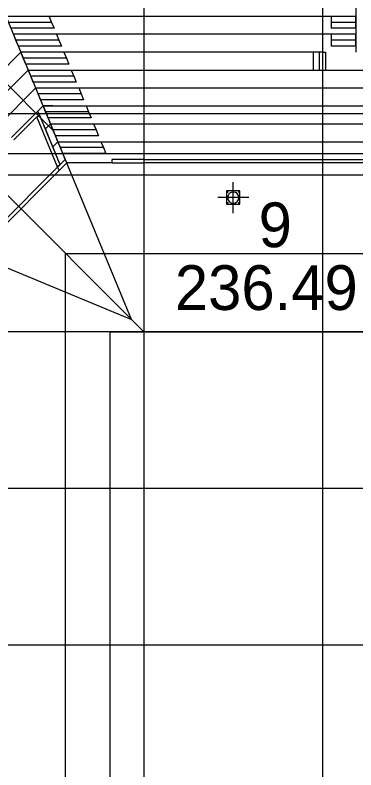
# Model space of a CAD drawing. Extents: x -264165 to -263575, y -1242333 to -1242036.
# Drawn here: x -263890.22 to -263874.98, y -1242131.46 to -1242097.73 of the extents above; entities that cross this region are included whole.
import ezdxf

# ---------------------------------------------------------------- set-up
doc = ezdxf.new("R2010")
doc.units = 0
for name, color, linetype in [('KFA_BODY_VYTYCOVAK', 7, 'Continuous'), ('KFA_HESCON_OSI_STAVBY', 7, 'Continuous'), ('KFA_SITUACIA_DRS_VYTYCOVAK_SEDA', 7, 'Continuous')]:
    doc.layers.add(name, color=color, linetype=linetype)

msp = doc.modelspace()

# ---------------------------------------------------------------- linework, layer by layer
at = {"layer": 'KFA_HESCON_OSI_STAVBY'}
for p, q in [((-263884.468, -1242080.447), (-263884.468, -1242248.737)), ((-263876.468, -1242080.447), (-263876.468, -1242248.737)), ((-263906.568, -1242084.832), (-263888.515, -1242102.885)), ((-263884.468, -1242111.882), (-263909.043, -1242087.307)), ((-263885.015, -1242111.335), (-263894.968, -1242087.307)), ((-263909.043, -1242101.382), (-263885.015, -1242111.335)), ((-263787.486, -1242102.132), (-263921.823, -1242102.132)), ((-263787.486, -1242103.932), (-263921.823, -1242103.932)), ((-263787.486, -1242104.882), (-263921.823, -1242104.882)), ((-263787.486, -1242111.882), (-263921.823, -1242111.882)), ((-263884.468, -1242111.882), (-263884.468, -1242111.882)), ((-263787.486, -1242118.882), (-263921.823, -1242118.882)), ((-263787.486, -1242125.882), (-263921.823, -1242125.882))]:
    msp.add_line(p, q, dxfattribs=at)
at = {"layer": 'KFA_SITUACIA_DRS_VYTYCOVAK_SEDA'}
for p, q in [((-263874.98, -1242096.982), (-263874.98, -1242097.782)), ((-263874.98, -1242096.982), (-263874.98, -1242097.782)), ((-263884.468, -1242097.782), (-263890.629, -1242097.782)), ((-263884.468, -1242097.782), (-263890.629, -1242097.782)), ((-263888.593, -1242098.049), (-263890.518, -1242098.049)), ((-263888.593, -1242098.049), (-263890.518, -1242098.049)), ((-263888.704, -1242097.782), (-263888.593, -1242098.049)), ((-263888.704, -1242097.782), (-263888.593, -1242098.049)), ((-263888.593, -1242098.049), (-263888.483, -1242098.316)), ((-263888.593, -1242098.049), (-263888.483, -1242098.316)), ((-263876.468, -1242097.782), (-263884.468, -1242097.782)), ((-263876.468, -1242097.782), (-263884.468, -1242097.782)), ((-263874.98, -1242097.782), (-263876.468, -1242097.782)), ((-263874.98, -1242097.782), (-263876.468, -1242097.782)), ((-263876.081, -1242097.782), (-263876.081, -1242098.049)), ((-263876.081, -1242097.782), (-263876.081, -1242098.049)), ((-263874.981, -1242098.049), (-263876.081, -1242098.049)), ((-263874.981, -1242098.049), (-263876.081, -1242098.049)), ((-263876.081, -1242098.049), (-263876.081, -1242098.316)), ((-263876.081, -1242098.049), (-263876.081, -1242098.316)), ((-263874.981, -1242098.049), (-263874.981, -1242097.782)), ((-263874.981, -1242098.049), (-263874.981, -1242097.782)), ((-263874.981, -1242098.316), (-263874.981, -1242098.049)), ((-263874.981, -1242098.316), (-263874.981, -1242098.049)), ((-263874.98, -1242097.782), (-263874.98, -1242098.582)), ((-263874.98, -1242097.782), (-263874.98, -1242098.582)), ((-263888.483, -1242098.316), (-263890.408, -1242098.316)), ((-263888.483, -1242098.316), (-263890.408, -1242098.316)), ((-263874.981, -1242098.316), (-263876.081, -1242098.316)), ((-263874.981, -1242098.316), (-263876.081, -1242098.316)), ((-263890.187, -1242098.849), (-263890.298, -1242098.582)), ((-263890.187, -1242098.849), (-263890.298, -1242098.582)), ((-263884.468, -1242098.582), (-263890.298, -1242098.582)), ((-263884.468, -1242098.582), (-263890.298, -1242098.582)), ((-263888.373, -1242098.582), (-263888.262, -1242098.849)), ((-263888.373, -1242098.582), (-263888.262, -1242098.849)), ((-263876.468, -1242098.582), (-263884.468, -1242098.582)), ((-263876.468, -1242098.582), (-263884.468, -1242098.582)), ((-263874.98, -1242098.582), (-263876.468, -1242098.582)), ((-263874.98, -1242098.582), (-263876.468, -1242098.582)), ((-263876.081, -1242098.582), (-263876.081, -1242098.849)), ((-263876.081, -1242098.582), (-263876.081, -1242098.849)), ((-263874.981, -1242098.849), (-263874.981, -1242098.582)), ((-263874.981, -1242098.849), (-263874.981, -1242098.582)), ((-263874.98, -1242098.582), (-263874.98, -1242099.382)), ((-263874.98, -1242098.582), (-263874.98, -1242099.382)), ((-263890.077, -1242099.116), (-263890.187, -1242098.849)), ((-263890.077, -1242099.116), (-263890.187, -1242098.849)), ((-263888.262, -1242098.849), (-263890.187, -1242098.849)), ((-263888.262, -1242098.849), (-263890.187, -1242098.849)), ((-263888.262, -1242098.849), (-263888.152, -1242099.116)), ((-263888.262, -1242098.849), (-263888.152, -1242099.116)), ((-263874.981, -1242098.849), (-263876.081, -1242098.849)), ((-263874.981, -1242098.849), (-263876.081, -1242098.849)), ((-263876.081, -1242098.849), (-263876.081, -1242099.116)), ((-263876.081, -1242098.849), (-263876.081, -1242099.116)), ((-263874.981, -1242099.116), (-263874.981, -1242098.849)), ((-263874.981, -1242099.116), (-263874.981, -1242098.849)), ((-263889.966, -1242099.382), (-263891.204, -1242100.62)), ((-263889.966, -1242099.382), (-263891.204, -1242100.62)), ((-263888.152, -1242099.116), (-263890.077, -1242099.116)), ((-263888.152, -1242099.116), (-263890.077, -1242099.116)), ((-263889.856, -1242099.649), (-263889.966, -1242099.382)), ((-263889.856, -1242099.649), (-263889.966, -1242099.382)), ((-263889.056, -1242099.382), (-263889.966, -1242099.382)), ((-263889.056, -1242099.382), (-263889.966, -1242099.382)), ((-263884.468, -1242099.382), (-263889.966, -1242099.382)), ((-263884.468, -1242099.382), (-263889.966, -1242099.382)), ((-263888.041, -1242099.382), (-263887.931, -1242099.649)), ((-263888.041, -1242099.382), (-263887.931, -1242099.649)), ((-263876.468, -1242099.382), (-263884.468, -1242099.382)), ((-263876.468, -1242099.382), (-263884.468, -1242099.382)), ((-263876.881, -1242100.182), (-263876.881, -1242099.382)), ((-263876.881, -1242100.182), (-263876.881, -1242099.382)), ((-263876.614, -1242100.182), (-263876.614, -1242099.382)), ((-263876.614, -1242100.182), (-263876.614, -1242099.382)), ((-263876.468, -1242099.382), (-263876.347, -1242099.382)), ((-263876.468, -1242099.382), (-263876.347, -1242099.382)), ((-263876.347, -1242099.382), (-263876.347, -1242100.182)), ((-263876.347, -1242099.382), (-263876.347, -1242100.182)), ((-263874.981, -1242099.116), (-263876.081, -1242099.116)), ((-263874.981, -1242099.116), (-263876.081, -1242099.116)), ((-263889.745, -1242099.916), (-263889.856, -1242099.649)), ((-263889.745, -1242099.916), (-263889.856, -1242099.649)), ((-263887.931, -1242099.649), (-263889.856, -1242099.649)), ((-263887.931, -1242099.649), (-263889.856, -1242099.649)), ((-263887.931, -1242099.649), (-263887.82, -1242099.916)), ((-263887.931, -1242099.649), (-263887.82, -1242099.916)), ((-263887.82, -1242099.916), (-263889.745, -1242099.916)), ((-263887.82, -1242099.916), (-263889.745, -1242099.916)), ((-263890.639, -1242101.186), (-263889.635, -1242100.182)), ((-263890.639, -1242101.186), (-263889.635, -1242100.182)), ((-263889.524, -1242100.449), (-263889.635, -1242100.182)), ((-263889.524, -1242100.449), (-263889.635, -1242100.182)), ((-263889.635, -1242100.182), (-263884.468, -1242100.182)), ((-263889.635, -1242100.182), (-263884.468, -1242100.182)), ((-263887.71, -1242100.182), (-263887.599, -1242100.449)), ((-263887.71, -1242100.182), (-263887.599, -1242100.449)), ((-263884.468, -1242100.182), (-263876.468, -1242100.182)), ((-263884.468, -1242100.182), (-263876.468, -1242100.182)), ((-263876.881, -1242100.182), (-263876.614, -1242100.182)), ((-263876.881, -1242100.182), (-263876.614, -1242100.182)), ((-263876.614, -1242100.182), (-263876.347, -1242100.182)), ((-263876.614, -1242100.182), (-263876.347, -1242100.182)), ((-263876.468, -1242100.182), (-263869.468, -1242100.182)), ((-263876.468, -1242100.182), (-263869.468, -1242100.182)), ((-263876.347, -1242100.182), (-263873.518, -1242100.182)), ((-263876.347, -1242100.182), (-263873.518, -1242100.182)), ((-263889.414, -1242100.716), (-263889.524, -1242100.449)), ((-263889.414, -1242100.716), (-263889.524, -1242100.449)), ((-263887.599, -1242100.449), (-263889.524, -1242100.449)), ((-263887.599, -1242100.449), (-263889.524, -1242100.449)), ((-263887.489, -1242100.716), (-263889.414, -1242100.716)), ((-263887.489, -1242100.716), (-263889.414, -1242100.716)), ((-263887.599, -1242100.449), (-263887.489, -1242100.716)), ((-263887.599, -1242100.449), (-263887.489, -1242100.716)), ((-263890.957, -1242102.636), (-263889.303, -1242100.982)), ((-263890.957, -1242102.636), (-263889.303, -1242100.982)), ((-263889.193, -1242101.249), (-263889.303, -1242100.982)), ((-263889.193, -1242101.249), (-263889.303, -1242100.982)), ((-263889.303, -1242100.982), (-263884.468, -1242100.982)), ((-263889.303, -1242100.982), (-263884.468, -1242100.982)), ((-263887.378, -1242100.982), (-263887.268, -1242101.249)), ((-263887.378, -1242100.982), (-263887.268, -1242101.249)), ((-263884.468, -1242100.982), (-263876.468, -1242100.982)), ((-263884.468, -1242100.982), (-263876.468, -1242100.982)), ((-263876.468, -1242100.982), (-263869.468, -1242100.982)), ((-263876.468, -1242100.982), (-263869.468, -1242100.982)), ((-263889.083, -1242101.516), (-263889.193, -1242101.249)), ((-263889.083, -1242101.516), (-263889.193, -1242101.249)), ((-263887.268, -1242101.249), (-263889.193, -1242101.249)), ((-263887.268, -1242101.249), (-263889.193, -1242101.249)), ((-263887.268, -1242101.249), (-263887.158, -1242101.516)), ((-263887.268, -1242101.249), (-263887.158, -1242101.516)), ((-263887.158, -1242101.516), (-263889.083, -1242101.516)), ((-263887.158, -1242101.516), (-263889.083, -1242101.516)), ((-263889.202, -1242102.012), (-263889.316, -1242102.127)), ((-263889.202, -1242102.012), (-263889.316, -1242102.127)), ((-263889.202, -1242102.012), (-263888.972, -1242101.782)), ((-263889.202, -1242102.012), (-263888.972, -1242101.782)), ((-263889.202, -1242102.012), (-263888.972, -1242101.782)), ((-263889.202, -1242102.012), (-263888.972, -1242101.782)), ((-263888.87, -1242102.812), (-263889.202, -1242102.012)), ((-263888.87, -1242102.812), (-263889.202, -1242102.012)), ((-263889.116, -1242102.219), (-263889.202, -1242102.012)), ((-263889.116, -1242102.219), (-263889.202, -1242102.012)), ((-263888.862, -1242102.049), (-263888.972, -1242101.782)), ((-263888.862, -1242102.049), (-263888.972, -1242101.782)), ((-263888.543, -1242101.782), (-263888.972, -1242101.782)), ((-263888.543, -1242101.782), (-263888.972, -1242101.782)), ((-263888.972, -1242101.782), (-263888.641, -1242102.582)), ((-263888.972, -1242101.782), (-263888.641, -1242102.582)), ((-263888.972, -1242101.782), (-263884.468, -1242101.782)), ((-263888.972, -1242101.782), (-263884.468, -1242101.782)), ((-263888.751, -1242102.316), (-263888.862, -1242102.049)), ((-263888.751, -1242102.316), (-263888.862, -1242102.049)), ((-263886.937, -1242102.049), (-263888.862, -1242102.049)), ((-263886.937, -1242102.049), (-263888.862, -1242102.049)), ((-263887.047, -1242101.782), (-263886.937, -1242102.049)), ((-263887.047, -1242101.782), (-263886.937, -1242102.049)), ((-263886.937, -1242102.049), (-263886.826, -1242102.316)), ((-263886.937, -1242102.049), (-263886.826, -1242102.316)), ((-263884.468, -1242101.782), (-263876.468, -1242101.782)), ((-263884.468, -1242101.782), (-263876.468, -1242101.782)), ((-263876.468, -1242101.782), (-263869.468, -1242101.782)), ((-263876.468, -1242101.782), (-263869.468, -1242101.782)), ((-263890.391, -1242103.201), (-263889.316, -1242102.127)), ((-263890.391, -1242103.201), (-263889.316, -1242102.127)), ((-263889.254, -1242102.277), (-263890.285, -1242103.307)), ((-263889.254, -1242102.277), (-263890.285, -1242103.307)), ((-263889.254, -1242102.277), (-263889.116, -1242102.219)), ((-263889.254, -1242102.277), (-263889.116, -1242102.219)), ((-263888.346, -1242104.469), (-263889.254, -1242102.277)), ((-263888.346, -1242104.469), (-263889.254, -1242102.277)), ((-263888.208, -1242104.412), (-263889.116, -1242102.219)), ((-263888.208, -1242104.412), (-263889.116, -1242102.219)), ((-263886.826, -1242102.316), (-263888.751, -1242102.316)), ((-263886.826, -1242102.316), (-263888.751, -1242102.316)), ((-263888.641, -1242102.582), (-263888.751, -1242102.316)), ((-263888.641, -1242102.582), (-263888.751, -1242102.316)), ((-263888.87, -1242102.812), (-263888.641, -1242102.582)), ((-263888.87, -1242102.812), (-263888.641, -1242102.582)), ((-263888.53, -1242102.849), (-263888.641, -1242102.582)), ((-263888.53, -1242102.849), (-263888.641, -1242102.582)), ((-263888.641, -1242102.582), (-263888.309, -1242103.382)), ((-263888.641, -1242102.582), (-263888.309, -1242103.382)), ((-263888.641, -1242102.582), (-263884.468, -1242102.582)), ((-263888.641, -1242102.582), (-263884.468, -1242102.582)), ((-263886.716, -1242102.582), (-263886.605, -1242102.849)), ((-263886.716, -1242102.582), (-263886.605, -1242102.849)), ((-263884.468, -1242102.582), (-263876.468, -1242102.582)), ((-263884.468, -1242102.582), (-263876.468, -1242102.582)), ((-263876.468, -1242102.582), (-263869.468, -1242102.582)), ((-263876.468, -1242102.582), (-263869.468, -1242102.582)), ((-263888.539, -1242103.612), (-263888.87, -1242102.812)), ((-263888.539, -1242103.612), (-263888.87, -1242102.812)), ((-263888.42, -1242103.116), (-263888.53, -1242102.849)), ((-263888.42, -1242103.116), (-263888.53, -1242102.849)), ((-263886.605, -1242102.849), (-263888.53, -1242102.849)), ((-263886.605, -1242102.849), (-263888.53, -1242102.849)), ((-263886.495, -1242103.116), (-263888.42, -1242103.116)), ((-263886.495, -1242103.116), (-263888.42, -1242103.116)), ((-263888.309, -1242103.382), (-263888.42, -1242103.116)), ((-263888.309, -1242103.382), (-263888.42, -1242103.116)), ((-263886.605, -1242102.849), (-263886.495, -1242103.116)), ((-263886.605, -1242102.849), (-263886.495, -1242103.116)), ((-263888.539, -1242103.612), (-263888.309, -1242103.382)), ((-263888.539, -1242103.612), (-263888.309, -1242103.382)), ((-263888.199, -1242103.649), (-263888.309, -1242103.382)), ((-263888.199, -1242103.649), (-263888.309, -1242103.382)), ((-263888.309, -1242103.382), (-263887.978, -1242104.182)), ((-263888.309, -1242103.382), (-263887.978, -1242104.182)), ((-263888.309, -1242103.382), (-263884.468, -1242103.382)), ((-263888.309, -1242103.382), (-263884.468, -1242103.382)), ((-263886.384, -1242103.382), (-263886.274, -1242103.649)), ((-263886.384, -1242103.382), (-263886.274, -1242103.649)), ((-263884.468, -1242103.382), (-263876.468, -1242103.382)), ((-263884.468, -1242103.382), (-263876.468, -1242103.382)), ((-263876.468, -1242103.382), (-263869.468, -1242103.382)), ((-263876.468, -1242103.382), (-263869.468, -1242103.382)), ((-263888.208, -1242104.412), (-263888.539, -1242103.612)), ((-263888.208, -1242104.412), (-263888.539, -1242103.612)), ((-263888.088, -1242103.916), (-263888.199, -1242103.649)), ((-263888.088, -1242103.916), (-263888.199, -1242103.649)), ((-263886.274, -1242103.649), (-263888.199, -1242103.649)), ((-263886.274, -1242103.649), (-263888.199, -1242103.649)), ((-263886.274, -1242103.649), (-263886.163, -1242103.916)), ((-263886.274, -1242103.649), (-263886.163, -1242103.916)), ((-263886.163, -1242103.916), (-263888.088, -1242103.916)), ((-263886.163, -1242103.916), (-263888.088, -1242103.916)), ((-263887.978, -1242104.182), (-263888.088, -1242103.916)), ((-263887.978, -1242104.182), (-263888.088, -1242103.916)), ((-263888.346, -1242104.469), (-263888.208, -1242104.412)), ((-263888.346, -1242104.469), (-263888.208, -1242104.412)), ((-263887.978, -1242104.182), (-263888.322, -1242104.527)), ((-263887.978, -1242104.182), (-263888.322, -1242104.527)), ((-263888.208, -1242104.412), (-263888.322, -1242104.527)), ((-263888.208, -1242104.412), (-263888.322, -1242104.527)), ((-263888.26, -1242104.677), (-263887.916, -1242104.332)), ((-263888.26, -1242104.677), (-263887.916, -1242104.332)), ((-263887.978, -1242104.182), (-263887.916, -1242104.332)), ((-263887.978, -1242104.182), (-263887.916, -1242104.332)), ((-263885.876, -1242104.332), (-263887.916, -1242104.332)), ((-263885.876, -1242104.332), (-263887.916, -1242104.332)), ((-263885.876, -1242104.332), (-263885.876, -1242104.182)), ((-263885.876, -1242104.332), (-263885.876, -1242104.182)), ((-263884.468, -1242104.182), (-263885.876, -1242104.182)), ((-263884.468, -1242104.182), (-263885.876, -1242104.182)), ((-263885.876, -1242104.332), (-263884.468, -1242104.332)), ((-263885.876, -1242104.332), (-263884.468, -1242104.332)), ((-263884.468, -1242104.182), (-263876.468, -1242104.182)), ((-263884.468, -1242104.182), (-263876.468, -1242104.182)), ((-263876.468, -1242104.332), (-263884.468, -1242104.332)), ((-263876.468, -1242104.332), (-263884.468, -1242104.332)), ((-263876.468, -1242104.182), (-263873.618, -1242104.182)), ((-263876.468, -1242104.182), (-263873.618, -1242104.182)), ((-263873.618, -1242104.332), (-263876.468, -1242104.332)), ((-263873.618, -1242104.332), (-263876.468, -1242104.332)), ((-263888.322, -1242104.527), (-263891.823, -1242108.028)), ((-263888.322, -1242104.527), (-263891.823, -1242108.028)), ((-263891.673, -1242108.09), (-263888.26, -1242104.677)), ((-263891.673, -1242108.09), (-263888.26, -1242104.677)), ((-263888.322, -1242104.527), (-263888.346, -1242104.469)), ((-263888.322, -1242104.527), (-263888.346, -1242104.469)), ((-263888.322, -1242104.527), (-263888.26, -1242104.677)), ((-263888.322, -1242104.527), (-263888.26, -1242104.677)), ((-263880.468, -1242106.577), (-263880.468, -1242105.187)), ((-263880.168, -1242105.582), (-263880.768, -1242105.582)), ((-263880.768, -1242105.582), (-263880.768, -1242106.182)), ((-263880.168, -1242106.182), (-263880.168, -1242105.582)), ((-263879.773, -1242105.882), (-263881.163, -1242105.882)), ((-263880.768, -1242106.182), (-263880.168, -1242106.182)), ((-263887.968, -1242108.382), (-263815.968, -1242108.382)), ((-263887.968, -1242220.382), (-263887.968, -1242108.382)), ((-263885.968, -1242111.882), (-263817.968, -1242111.882)), ((-263885.968, -1242216.882), (-263885.968, -1242111.882))]:
    msp.add_line(p, q, dxfattribs=at)
for centre, radius, start, end in [((-263880.718, -1242105.632), 0.018, 90, 180), ((-263880.718, -1242105.632), 0.018, 180, 270), ((-263880.718, -1242105.632), 0.018, 0, 90), ((-263880.718, -1242105.632), 0.018, 270, 0), ((-263880.468, -1242105.882), 0.25, 90, 180), ((-263880.468, -1242105.882), 0.25, 0, 90), ((-263880.218, -1242105.632), 0.018, 90, 180), ((-263880.218, -1242105.632), 0.018, 180, 270), ((-263880.218, -1242105.632), 0.018, 0, 90), ((-263880.218, -1242105.632), 0.018, 270, 0), ((-263880.718, -1242106.132), 0.018, 90, 180), ((-263880.718, -1242106.132), 0.018, 180, 270), ((-263880.468, -1242105.882), 0.25, 180, 270), ((-263880.718, -1242106.132), 0.018, 0, 90), ((-263880.718, -1242106.132), 0.018, 270, 0), ((-263880.468, -1242105.882), 0.25, 270, 0), ((-263880.218, -1242106.132), 0.018, 90, 180), ((-263880.218, -1242106.132), 0.018, 180, 270), ((-263880.218, -1242106.132), 0.018, 0, 90), ((-263880.218, -1242106.132), 0.018, 270, 0)]:
    msp.add_arc(centre, radius, start, end, dxfattribs=at)

# ---------------------------------------------------------------- texts
at = {"layer": 'KFA_BODY_VYTYCOVAK'}
for s, p in [('9', (-263879.333, -1242108.098)), ('236.49', (-263883.077, -1242110.904))]:
    msp.add_text(s, height=2, dxfattribs=at).set_placement(p)

doc.saveas('drawing.dxf')
